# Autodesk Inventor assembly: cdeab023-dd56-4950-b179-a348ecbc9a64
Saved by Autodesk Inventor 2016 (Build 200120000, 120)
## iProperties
Created: 2017-06
Part Number: cdeab023-dd56-4950-b179-a348ecbc9a64
Document SubType Name: Assembly
Designer: Administrator
Author: Administrator
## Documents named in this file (2)
- c:\worker\convert-fusion-jun-2017\tmp\job-1\12\output\files\680d4b69-c182-4e82-8b38-9dde0e804810\cdeab023-dd56-4950-b179-a348ecbc9a64.iam
- c:\worker\convert-fusion-jun-2017\tmp\job-1\12\output\files\680d4b69-c182-4e82-8b38-9dde0e804810\Ensamble.iam
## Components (1 placed, 1 different names)
1. Ensamble:1 [sub-assembly]
